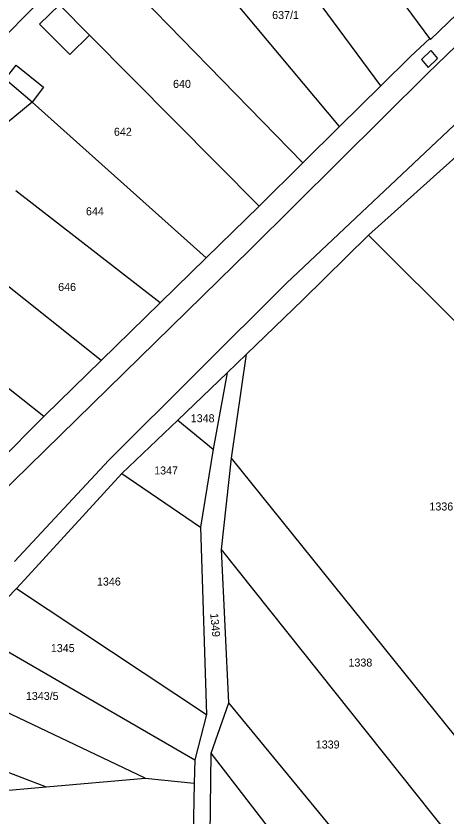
# Model space of a CAD drawing. Extents: x -563148 to -561712, y -1182311 to -1179502.
# Drawn here: x -562687.9 to -562607.2, y -1181313.6 to -1181163.6 of the extents above; entities that cross this region are included whole.
import ezdxf

# ---------------------------------------------------------------- set-up
doc = ezdxf.new("R2010")
doc.units = 0
for name, color, linetype in [('Vrstva 55', 7, 'Continuous'), ('Vrstva 56', 7, 'Continuous'), ('Vrstva 57', 7, 'Continuous')]:
    doc.layers.add(name, color=color, linetype=linetype)

msp = doc.modelspace()

# ---------------------------------------------------------------- linework, layer by layer
at = {"layer": 'Vrstva 55'}
for p, q in [((-562610.4, -1181167.86), (-562651.1, -1181112.34)), ((-562619.58, -1181176.7), (-562644.59, -1181142.91)), ((-562634.17, -1181191.14), (-562673.87, -1181150.45)), ((-562627.3, -1181184.34), (-562649.15, -1181158.22)), ((-562610.3, -1181168.05), (-562602.56, -1181160.59)), ((-562684.12, -1181161.48), (-562694.42, -1181171.87)), ((-562674.15, -1181167.26), (-562679.77, -1181161.53)), ((-562642.39, -1181199.26), (-562674.15, -1181167.26)), ((-562614.01, -1181171.2), (-562610.4, -1181167.86)), ((-562610.4, -1181167.86), (-562610.3, -1181168.05)), ((-562619.58, -1181176.7), (-562614.01, -1181171.2)), ((-562684.9, -1181179.76), (-562689.99, -1181175.45)), ((-562627.3, -1181184.34), (-562619.58, -1181176.7)), ((-562684.9, -1181179.76), (-562694.91, -1181188)), ((-562652.3, -1181209), (-562684.9, -1181179.76)), ((-562634.17, -1181191.14), (-562627.3, -1181184.34)), ((-562621.89, -1181204.72), (-562600.47, -1181185.46)), ((-562642.39, -1181199.26), (-562634.17, -1181191.14)), ((-562660.91, -1181217.41), (-562687.95, -1181196.38)), ((-562647.29, -1181204.11), (-562642.39, -1181199.26)), ((-562652.3, -1181209), (-562647.29, -1181204.11)), ((-562634.17, -1181216.87), (-562621.89, -1181204.72)), ((-562578.79, -1181247.75), (-562621.89, -1181204.72)), ((-562671.98, -1181228.22), (-562696.91, -1181208.34)), ((-562660.91, -1181217.41), (-562652.3, -1181209)), ((-562644.75, -1181227.03), (-562634.17, -1181216.87)), ((-562671.98, -1181228.22), (-562660.91, -1181217.41)), ((-562644.75, -1181227.03), (-562648.36, -1181230.5)), ((-562647.59, -1181246.52), (-562644.75, -1181227.03)), ((-562682.54, -1181238.53), (-562671.98, -1181228.22)), ((-562686.67, -1181235.6), (-562693.57, -1181230.16)), ((-562648.36, -1181230.5), (-562657.63, -1181239.4)), ((-562648.36, -1181230.5), (-562651.01, -1181244.84)), ((-562682.72, -1181238.72), (-562686.67, -1181235.6)), ((-562695.59, -1181251.65), (-562682.72, -1181238.72)), ((-562682.72, -1181238.72), (-562682.54, -1181238.53)), ((-562657.63, -1181239.4), (-562668.09, -1181249.43)), ((-562657.63, -1181239.4), (-562651.01, -1181244.84)), ((-562651.01, -1181244.84), (-562653.37, -1181259.44)), ((-562649.41, -1181263.64), (-562647.59, -1181246.52)), ((-562597.76, -1181308.43), (-562647.59, -1181246.52)), ((-562668.09, -1181249.43), (-562685.66, -1181268.59)), ((-562668.09, -1181249.43), (-562653.37, -1181259.44)), ((-562653.37, -1181259.44), (-562652.27, -1181294.58)), ((-562603.79, -1181320.96), (-562649.41, -1181263.64)), ((-562648.08, -1181292.38), (-562649.41, -1181263.64)), ((-562685.66, -1181268.59), (-562687.87, -1181270.93)), ((-562687.87, -1181270.93), (-562695.79, -1181279.15)), ((-562687.87, -1181270.93), (-562652.27, -1181294.58)), ((-562695.79, -1181279.15), (-562654.44, -1181303.1)), ((-562663.74, -1181306.52), (-562703.62, -1181287.57)), ((-562651.36, -1181301.81), (-562648.08, -1181292.38)), ((-562612.86, -1181335.13), (-562648.08, -1181292.38)), ((-562652.27, -1181294.58), (-562654.44, -1181303.1)), ((-562712.25, -1181296.57), (-562682.3, -1181308.15)), ((-562651.72, -1181329.8), (-562651.36, -1181301.81)), ((-562618.93, -1181343.8), (-562651.36, -1181301.81)), ((-562654.44, -1181303.1), (-562654.53, -1181307.42)), ((-562682.3, -1181308.15), (-562663.74, -1181306.52)), ((-562663.74, -1181306.52), (-562654.53, -1181307.42)), ((-562698, -1181309.53), (-562682.3, -1181308.15)), ((-562654.53, -1181307.42), (-562654.93, -1181327))]:
    msp.add_line(p, q, dxfattribs=at)
at = {"layer": 'Vrstva 56'}
for p, q in [((-562610.85, -1181174.41), (-562577.75, -1181142.42)), ((-562683.51, -1181165.18), (-562679.77, -1181161.53)), ((-562677.86, -1181170.87), (-562683.51, -1181165.18)), ((-562674.15, -1181167.26), (-562677.86, -1181170.87)), ((-562610.21, -1181170.11), (-562611.93, -1181171.8)), ((-562610.21, -1181170.11), (-562608.96, -1181171.61)), ((-562611.93, -1181171.8), (-562610.71, -1181173.26)), ((-562608.96, -1181171.61), (-562610.71, -1181173.26)), ((-562689.99, -1181175.45), (-562687.93, -1181172.87)), ((-562687.93, -1181172.87), (-562682.77, -1181176.96)), ((-562644.07, -1181207.39), (-562610.85, -1181174.41)), ((-562682.77, -1181176.96), (-562684.9, -1181179.76)), ((-562603.7, -1181182.1), (-562637.26, -1181213.74)), ((-562699.87, -1181262.05), (-562644.07, -1181207.39)), ((-562637.26, -1181213.74), (-562670.54, -1181246.93)), ((-562670.54, -1181246.93), (-562688.23, -1181265.89))]:
    msp.add_line(p, q, dxfattribs=at)

# ---------------------------------------------------------------- texts
at = {"layer": 'Vrstva 57'}
for s, p in [('637/1', (-562639.94, -1181164.2)), ('640', (-562658.51, -1181177.11)), ('642', (-562669.59, -1181186.09)), ('644', (-562674.83, -1181200.99)), ('646', (-562680.04, -1181215.18)), ('1348', (-562655.2, -1181239.79)), ('1347', (-562662.05, -1181249.58)), ('1336', (-562610.47, -1181256.33)), ('1346', (-562672.77, -1181270.4)), ('1345', (-562681.41, -1181282.88)), ('1338', (-562625.64, -1181285.59)), ('1343/5', (-562686.09, -1181291.85)), ('1339', (-562631.77, -1181300.95))]:
    msp.add_text(s, height=1.5, dxfattribs=at).set_placement(p)
msp.add_text('1349', height=1.5, rotation=275.0345, dxfattribs=at).set_placement((-562651.55, -1181275.66))

doc.saveas('drawing.dxf')
